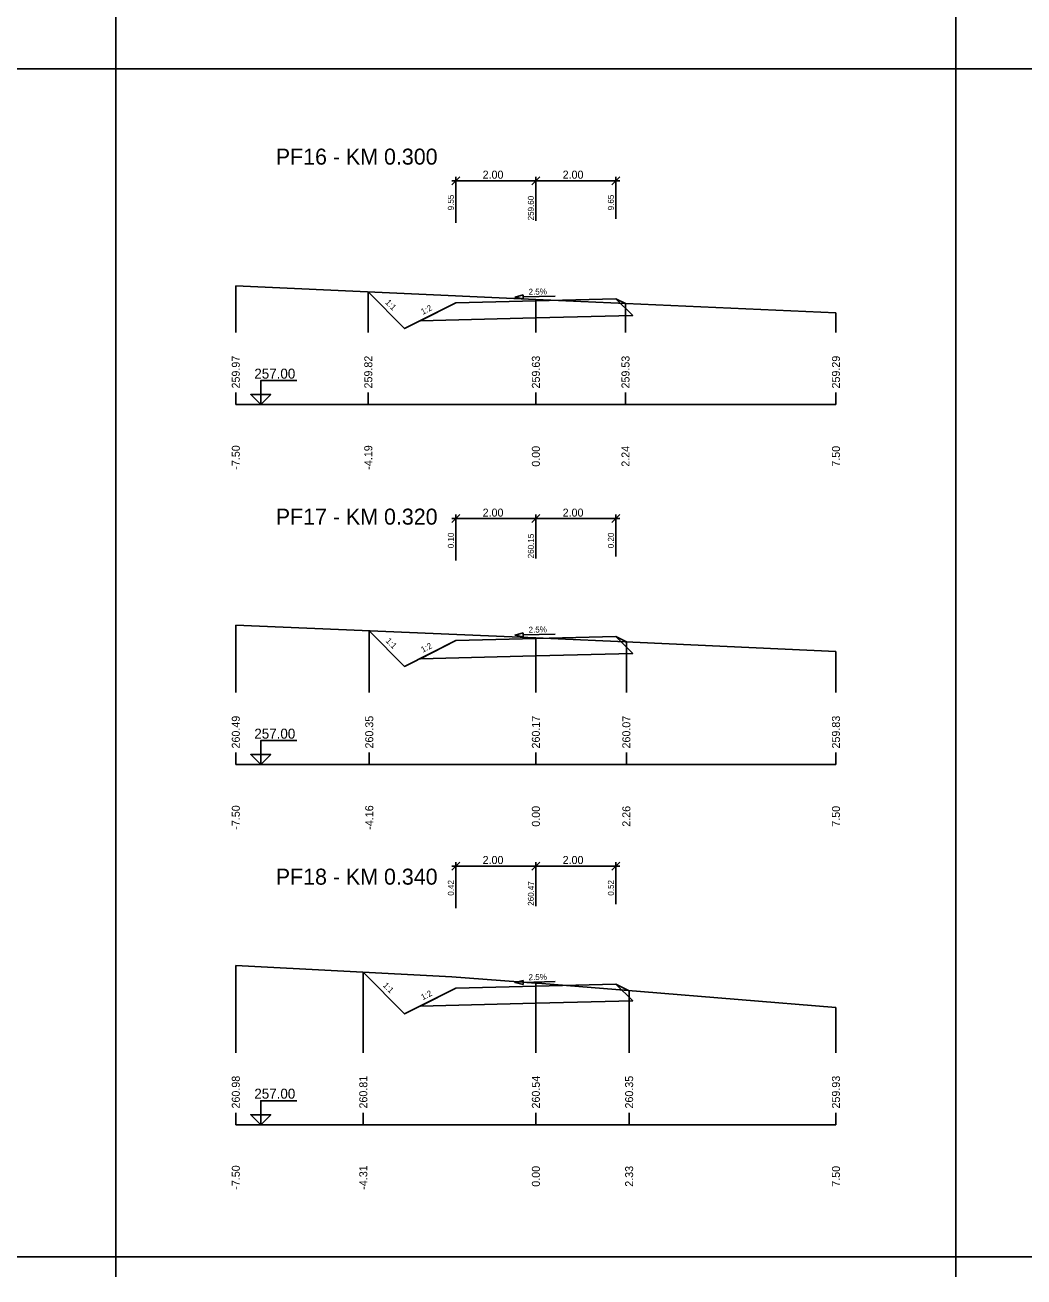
# Model space of a CAD drawing. Extents: x -1895 to 2525, y -19 to 585.
# Drawn here: x -862.6 to -613, y -19.1 to 293.9 of the extents above; entities that cross this region are included whole.
import ezdxf

# ---------------------------------------------------------------- set-up
doc = ezdxf.new("R2010")
doc.units = 0
for name, color, linetype in [('KOTA', 7, 'Continuous'), ('KOTA_DELKY', 7, 'Continuous'), ('KOTA_DELKY_CONT', 7, 'Continuous'), ('NS_TELESO_VOZOVKY', 7, 'Continuous'), ('NS_V_PF', 7, 'Continuous'), ('REZY_PF_PUVODNI', 7, 'Continuous'), ('SESTAVY_REZU_PF', 7, 'Continuous'), ('SKLON', 7, 'Continuous'), ('SVK', 7, 'Continuous')]:
    doc.layers.add(name, color=color, linetype=linetype)

msp = doc.modelspace()

# ---------------------------------------------------------------- linework, layer by layer
for p, q in [((-839.95, 287.93), (-839.95, 277.93)), ((-839.95, 287.93), (-839.95, 277.93)), ((-839.95, 287.93), (-839.95, 277.93)), ((-839.95, 287.93), (-839.95, 277.93)), ((-629.95, 287.93), (-629.95, 277.93)), ((-629.95, 287.93), (-629.95, 277.93)), ((-629.95, 287.93), (-629.95, 277.93)), ((-629.95, 287.93), (-629.95, 277.93)), ((-834.95, 282.93), (-844.95, 282.93)), ((-834.95, 282.93), (-844.95, 282.93)), ((-834.95, 282.93), (-844.95, 282.93)), ((-834.95, 282.93), (-844.95, 282.93)), ((-624.95, 282.93), (-634.95, 282.93)), ((-624.95, 282.93), (-634.95, 282.93)), ((-624.95, 282.93), (-634.95, 282.93)), ((-624.95, 282.93), (-634.95, 282.93)), ((-839.95, -9.07), (-839.95, -19.07)), ((-839.95, -9.07), (-839.95, -19.07)), ((-629.95, -9.07), (-629.95, -19.07)), ((-629.95, -9.07), (-629.95, -19.07)), ((-834.95, -14.07), (-844.95, -14.07)), ((-834.95, -14.07), (-844.95, -14.07)), ((-624.95, -14.07), (-634.95, -14.07)), ((-624.95, -14.07), (-634.95, -14.07))]:
    msp.add_line(p, q)
for points in [[(-1049.95, 579.93), (-839.95, 579.93), (-839.95, 282.93), (-1049.95, 282.93)], [(-839.95, 579.93), (-629.95, 579.93), (-629.95, 282.93), (-839.95, 282.93)], [(-629.95, 579.93), (-419.95, 579.93), (-419.95, 282.93), (-629.95, 282.93)], [(-1049.95, 282.93), (-839.95, 282.93), (-839.95, -14.07), (-1049.95, -14.07)], [(-839.95, 282.93), (-629.95, 282.93), (-629.95, -14.07), (-839.95, -14.07)], [(-629.95, 282.93), (-419.95, 282.93), (-419.95, -14.07), (-629.95, -14.07)]]:
    msp.add_lwpolyline(points, close=True)
at = {"layer": 'KOTA'}
for points in [[(-803.73, 201.5), (-806.23, 201.5), (-803.73, 199), (-803.73, 205), (-794.73, 205)], [(-803.73, 199), (-801.23, 201.5), (-803.73, 201.5)], [(-803.73, 111.5), (-806.23, 111.5), (-803.73, 109), (-803.73, 115), (-794.73, 115)], [(-803.73, 109), (-801.23, 111.5), (-803.73, 111.5)], [(-803.73, 21.5), (-806.23, 21.5), (-803.73, 19), (-803.73, 25), (-794.73, 25)], [(-803.73, 19), (-801.23, 21.5), (-803.73, 21.5)]]:
    msp.add_lwpolyline(points, dxfattribs=at)
at = {"layer": 'KOTA_DELKY'}
for points in [[(-755.95, 253.99), (-753.95, 255.99)], [(-755.95, 254.99), (-733.95, 254.99)], [(-754.95, 244.49), (-754.95, 255.99)], [(-735.95, 253.99), (-733.95, 255.99)], [(-735.95, 253.99), (-733.95, 255.99)], [(-735.95, 254.99), (-713.95, 254.99)], [(-734.95, 244.99), (-734.95, 255.99)], [(-734.95, 244.99), (-734.95, 255.99)], [(-715.95, 253.99), (-713.95, 255.99)], [(-714.95, 245.49), (-714.95, 255.99)], [(-755.95, 169.51), (-753.95, 171.51)], [(-755.95, 170.51), (-733.95, 170.51)], [(-754.95, 160.01), (-754.95, 171.51)], [(-735.95, 169.51), (-733.95, 171.51)], [(-735.95, 169.51), (-733.95, 171.51)], [(-735.95, 170.51), (-713.95, 170.51)], [(-734.95, 160.51), (-734.95, 171.51)], [(-734.95, 160.51), (-734.95, 171.51)], [(-715.95, 169.51), (-713.95, 171.51)], [(-714.95, 161.01), (-714.95, 171.51)], [(-755.95, 82.66), (-753.95, 84.66)], [(-754.95, 73.16), (-754.95, 84.66)], [(-735.95, 82.66), (-733.95, 84.66)], [(-735.95, 82.66), (-733.95, 84.66)], [(-734.95, 73.66), (-734.95, 84.66)], [(-734.95, 73.66), (-734.95, 84.66)], [(-715.95, 82.66), (-713.95, 84.66)], [(-714.95, 74.16), (-714.95, 84.66)], [(-755.95, 83.66), (-733.95, 83.66)], [(-735.95, 83.66), (-713.95, 83.66)]]:
    msp.add_lwpolyline(points, dxfattribs=at)
at = {"layer": 'NS_TELESO_VOZOVKY'}
for points in [[(-734.95, 224.99), (-714.95, 225.49), (-714.95, 225.49), (-710.75, 221.3), (-734.95, 220.69), (-763.89, 219.97), (-754.95, 224.49), (-754.95, 224.49), (-734.95, 224.99)], [(-734.95, 140.51), (-714.95, 141.01), (-714.95, 141.01), (-710.75, 136.82), (-734.95, 136.21), (-763.89, 135.49), (-754.95, 140.01), (-754.95, 140.01), (-734.95, 140.51)], [(-734.95, 53.66), (-714.95, 54.16), (-714.95, 54.16), (-710.75, 49.96), (-734.95, 49.36), (-763.89, 48.63), (-754.95, 53.16), (-754.95, 53.16), (-734.95, 53.66)]]:
    msp.add_lwpolyline(points, dxfattribs=at)
at = {"layer": 'NS_V_PF'}
for points in [[(-776.83, 227.19), (-767.76, 218.02), (-754.95, 224.49), (-754.95, 224.49), (-734.95, 224.99), (-714.95, 225.49), (-714.95, 225.49), (-712.55, 224.3)], [(-776.59, 142.46), (-767.76, 133.54), (-754.95, 140.01), (-754.95, 140.01), (-734.95, 140.51), (-714.95, 141.01), (-714.95, 141.01), (-712.34, 139.71)], [(-778.08, 57.11), (-767.76, 46.68), (-754.95, 53.16), (-754.95, 53.16), (-734.95, 53.66), (-714.95, 54.16), (-714.95, 54.16), (-711.64, 52.5)]]:
    msp.add_lwpolyline(points, dxfattribs=at)
at = {"layer": 'REZY_PF_PUVODNI'}
for points in [[(-809.95, 228.68), (-734.95, 225.3), (-659.95, 221.93)], [(-809.95, 143.88), (-734.95, 140.68), (-708.85, 139.56), (-659.95, 137.3)], [(-809.95, 58.77), (-755.94, 55.96), (-734.95, 54.39), (-733.48, 54.28), (-708.79, 52.27), (-659.95, 48.28)]]:
    msp.add_lwpolyline(points, dxfattribs=at)
at = {"layer": 'SESTAVY_REZU_PF'}
for points in [[(-809.95, 199), (-659.95, 199)], [(-809.95, 109), (-659.95, 109)], [(-809.95, 19), (-659.95, 19)]]:
    msp.add_lwpolyline(points, dxfattribs=at)
at = {"layer": 'SKLON'}
for points in [[(-738.16, 226.41), (-740.15, 225.86), (-738.14, 225.41), (-738.16, 226.41)], [(-738.15, 225.91), (-730.15, 226.11)], [(-738.16, 141.93), (-740.15, 141.38), (-738.14, 140.93), (-738.16, 141.93)], [(-738.15, 141.43), (-730.15, 141.63)], [(-738.16, 55.08), (-740.15, 54.53), (-738.14, 54.08), (-738.16, 55.08)], [(-738.15, 54.58), (-730.15, 54.78)]]:
    msp.add_lwpolyline(points, dxfattribs=at)
at = {"layer": 'SVK'}
for points in [[(-809.95, 217), (-809.95, 228.68)], [(-776.83, 217), (-776.83, 227.19)], [(-734.95, 217), (-734.95, 225.3)], [(-712.55, 217), (-712.55, 224.3)], [(-659.95, 217), (-659.95, 221.93)], [(-809.95, 199), (-809.95, 202)], [(-776.83, 199), (-776.83, 202)], [(-734.95, 199), (-734.95, 202)], [(-712.55, 199), (-712.55, 202)], [(-659.95, 199), (-659.95, 202)], [(-809.95, 127), (-809.95, 143.88)], [(-776.59, 127), (-776.59, 142.46)], [(-734.95, 127), (-734.95, 140.68)], [(-712.34, 127), (-712.34, 139.71)], [(-659.95, 127), (-659.95, 137.3)], [(-809.95, 109), (-809.95, 112)], [(-776.59, 109), (-776.59, 112)], [(-734.95, 109), (-734.95, 112)], [(-712.34, 109), (-712.34, 112)], [(-659.95, 109), (-659.95, 112)], [(-809.95, 37), (-809.95, 58.77)], [(-778.08, 37), (-778.08, 57.11)], [(-734.95, 37), (-734.95, 54.39)], [(-711.64, 37), (-711.64, 52.5)], [(-659.95, 37), (-659.95, 48.28)], [(-809.95, 19), (-809.95, 22)], [(-778.08, 19), (-778.08, 22)], [(-734.95, 19), (-734.95, 22)], [(-711.64, 19), (-711.64, 22)], [(-659.95, 19), (-659.95, 22)]]:
    msp.add_lwpolyline(points, dxfattribs=at)

# ---------------------------------------------------------------- texts
at = {"layer": 'KOTA'}
for p in [(-805.31, 205.5), (-805.31, 115.5), (-805.31, 25.5)]:
    msp.add_text('257.00', height=2.5, dxfattribs=at).set_placement(p)
at = {"layer": 'KOTA_DELKY'}
for p in [(-748.26, 255.49), (-728.26, 255.49), (-748.26, 171.01), (-728.26, 171.01), (-748.26, 84.16), (-728.26, 84.16)]:
    msp.add_text('2.00', height=2, dxfattribs=at).set_placement(p)
at = {"layer": 'KOTA_DELKY_CONT'}
for s, p in [('9.55', (-755.45, 247.58)), ('259.60', (-735.45, 245.07)), ('9.65', (-715.45, 247.58)), ('0.10', (-755.45, 163.1)), ('260.15', (-735.45, 160.59)), ('0.20', (-715.45, 163.1)), ('0.42', (-755.45, 76.25)), ('260.47', (-735.45, 73.73)), ('0.52', (-715.45, 76.25))]:
    msp.add_text(s, height=1.5, rotation=90, dxfattribs=at).set_placement(p)
at = {"layer": 'SESTAVY_REZU_PF'}
for s, p in [('PF16 - KM 0.300', (-799.95, 259)), ('PF17 - KM 0.320', (-799.95, 169)), ('PF18 - KM 0.340', (-799.95, 79))]:
    msp.add_text(s, height=4, dxfattribs=at).set_placement(p)
at = {"layer": 'SKLON'}
for s, rotation, p in [('2.5%', 1.4321, (-736.75, 226.45)), ('1:1', 314.7121, (-772.69, 224.43)), ('1:2', 26.8233, (-763.21, 221.44)), ('2.5%', 1.4321, (-736.75, 141.97)), ('1:1', 314.7121, (-772.57, 139.82)), ('1:2', 26.8233, (-763.21, 136.96)), ('2.5%', 1.4321, (-736.75, 55.11)), ('1:1', 314.7121, (-773.32, 53.72)), ('1:2', 26.8233, (-763.21, 50.1))]:
    msp.add_text(s, height=1.5, rotation=rotation, dxfattribs=at).set_placement(p)
at = {"layer": 'SVK'}
for s, p in [(' 259.97', (-808.95, 202.3)), (' 259.82', (-775.83, 202.3)), (' 259.63', (-733.95, 202.3)), (' 259.53', (-711.55, 202.3)), (' 259.29', (-658.95, 202.3)), (' -7.50', (-808.95, 182)), (' -4.19', (-775.83, 182)), ('  0.00', (-733.95, 182)), ('  2.24', (-711.55, 182)), ('  7.50', (-658.95, 182)), (' 260.49', (-808.95, 112.3)), (' 260.35', (-775.59, 112.3)), (' 260.17', (-733.95, 112.3)), (' 260.07', (-711.34, 112.3)), (' 259.83', (-658.95, 112.3)), (' -7.50', (-808.95, 92)), (' -4.16', (-775.59, 92)), ('  0.00', (-733.95, 92)), ('  2.26', (-711.34, 92)), ('  7.50', (-658.95, 92)), (' 260.98', (-808.95, 22.3)), (' 260.81', (-777.08, 22.3)), (' 260.54', (-733.95, 22.3)), (' 260.35', (-710.64, 22.3)), (' 259.93', (-658.95, 22.3)), (' -7.50', (-808.95, 2)), (' -4.31', (-777.08, 2)), ('  0.00', (-733.95, 2)), ('  2.33', (-710.64, 2)), ('  7.50', (-658.95, 2))]:
    msp.add_text(s, height=2, rotation=90, dxfattribs=at).set_placement(p)

doc.saveas('drawing.dxf')
